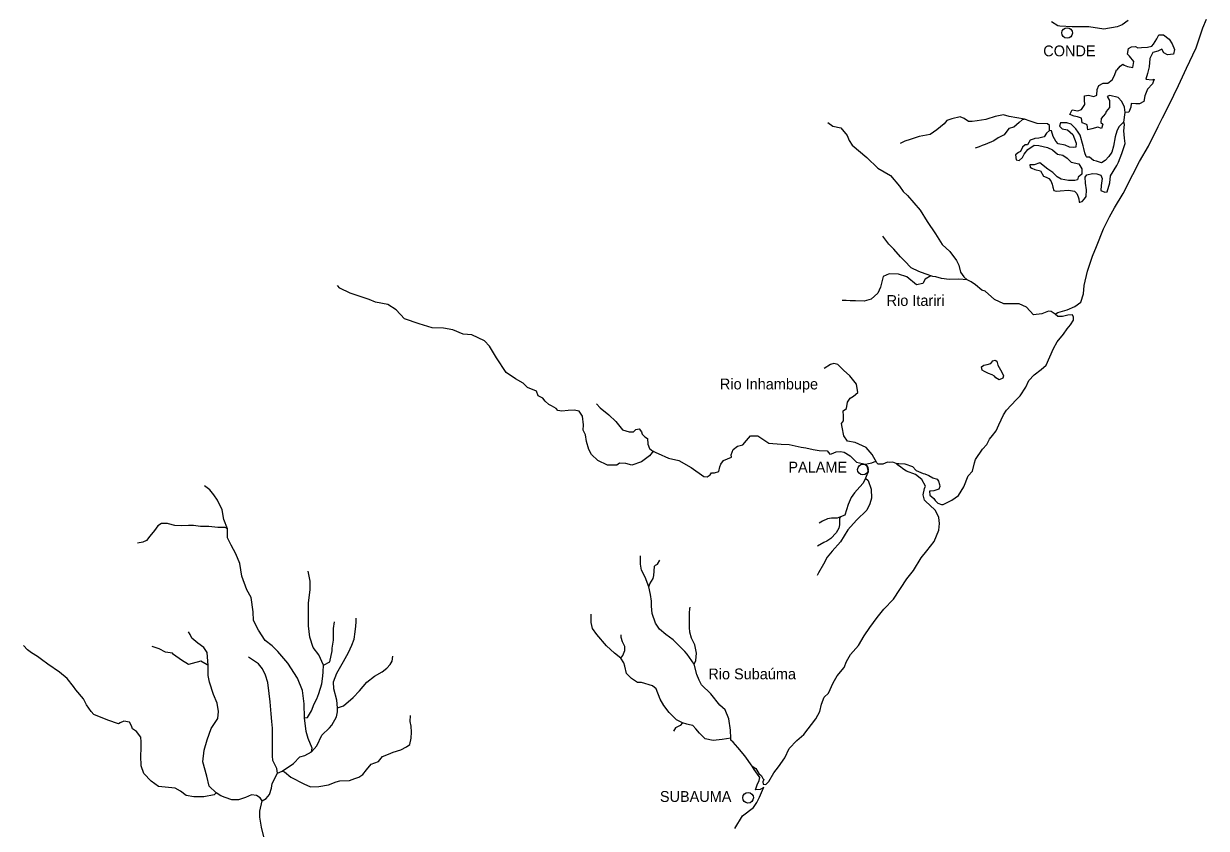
# Model space of a CAD drawing. Extents: x 662444 to 1640468, y 7452018 to 9606170.
# Drawn here: x 1241764 to 1315315, y 8633623 to 8683681 of the extents above; entities that cross this region are included whole.
import ezdxf

# ---------------------------------------------------------------- set-up
doc = ezdxf.new("R2010")
doc.units = 0
for name, color, linetype in [('Level 1', 7, 'Continuous'), ('Level 2', 7, 'Continuous'), ('Level 3', 7, 'Continuous')]:
    doc.layers.add(name, color=color, linetype=linetype)

msp = doc.modelspace()

# ---------------------------------------------------------------- linework, layer by layer
at = {"layer": 'Level 1'}
msp.add_line((1300438, 8667746), (1300438, 8667746), dxfattribs=at)
for points in [[(1310445, 8683882), (1310086, 8683602), (1309776, 8683487), (1308948, 8683342), (1308007, 8683490), (1307524, 8683492), (1306963, 8683473), (1306206, 8683515), (1306075, 8683552), (1305686, 8683797)], [(1311166, 8675098), (1311719, 8676053), (1312312, 8677286), (1312590, 8677825), (1312996, 8678628), (1313298, 8679222), (1313589, 8679839), (1314090, 8680919), (1314684, 8682174), (1315091, 8683412), (1315315, 8683964)], [(1310188, 8677544), (1310270, 8678155), (1310235, 8678490), (1310069, 8678840), (1309823, 8679081), (1309321, 8679217), (1309155, 8679155), (1309291, 8678906), (1309290, 8678460), (1309085, 8678209), (1309050, 8678098), (1308902, 8677924), (1308767, 8677782), (1308760, 8677537), (1308878, 8677423), (1308794, 8677157), (1308565, 8677241), (1308200, 8677129), (1307946, 8677080), (1307910, 8677393), (1307823, 8677429), (1307584, 8677502), (1307548, 8677804), (1307308, 8677888), (1307090, 8677916), (1306829, 8678024), (1306968, 8678310), (1307330, 8678267), (1307551, 8678350), (1307757, 8678657), (1307731, 8678914), (1307739, 8679193), (1307993, 8679242), (1308320, 8679144), (1308498, 8679239), (1308529, 8679584), (1308634, 8679827), (1308902, 8679976), (1309188, 8679979), (1309468, 8680184), (1309607, 8680448), (1309737, 8680801), (1309770, 8680811), (1309963, 8681029), (1310131, 8681170), (1310195, 8681090), (1310412, 8681006), (1310752, 8680963), (1310795, 8681330), (1310540, 8681649), (1310411, 8681787), (1310476, 8682142), (1310665, 8682237), (1310918, 8682264), (1311059, 8682182), (1311279, 8682187), (1311653, 8682211), (1311918, 8682270), (1312032, 8682401), (1312227, 8682731), (1312366, 8682983), (1312652, 8682987), (1313007, 8682710), (1313197, 8682415), (1313330, 8682065), (1313279, 8681788), (1312893, 8681731), (1312666, 8681871), (1312551, 8682086), (1312295, 8681970), (1311985, 8681878), (1311799, 8681504), (1311753, 8681004), (1311664, 8680582), (1311556, 8680228), (1311951, 8680195), (1312073, 8680237), (1311966, 8679927), (1311649, 8679601), (1311495, 8679181), (1311431, 8678838), (1311153, 8678700), (1310922, 8678684), (1310648, 8678713), (1310620, 8678480), (1310502, 8678182), (1310270, 8678155)], [(1305561, 8677032), (1305559, 8677355), (1305441, 8677447), (1304793, 8677476), (1304358, 8677610), (1303999, 8677742), (1303059, 8677912), (1302710, 8678011), (1302180, 8677902), (1301659, 8677737), (1301604, 8677717), (1301052, 8677631), (1300744, 8677594), (1300524, 8677589), (1300255, 8677786), (1300005, 8677882), (1299496, 8677761), (1299186, 8677647), (1299005, 8677440), (1298556, 8677084), (1298142, 8676794), (1297447, 8676656), (1296893, 8676470), (1296560, 8676367), (1296271, 8676230)], [(1303999, 8677742), (1303965, 8677721), (1303855, 8677701), (1303674, 8677528), (1303348, 8677235), (1303038, 8677154), (1302732, 8676772), (1302364, 8676581), (1302096, 8676388), (1301552, 8676168), (1301363, 8676106), (1301185, 8676022), (1300941, 8675928)], [(1306639, 8677505), (1306244, 8677504), (1306184, 8677305), (1306344, 8677145), (1306683, 8677080), (1307005, 8676792), (1307221, 8676251), (1307203, 8676007), (1307027, 8675967), (1306808, 8676006), (1306526, 8676125), (1306100, 8676214), (1305950, 8676363), (1305793, 8676669), (1305681, 8677006), (1305561, 8677032), (1305370, 8676869), (1305222, 8676650), (1304900, 8676547), (1304647, 8676532), (1304614, 8676510), (1304359, 8676439), (1304198, 8676142), (1304044, 8676147), (1303887, 8676006), (1303747, 8675731), (1303625, 8675667), (1303456, 8675515), (1303492, 8675202), (1303677, 8675164), (1303880, 8675359), (1303995, 8675557), (1304223, 8675852), (1304603, 8676121), (1304888, 8676102), (1305445, 8675975), (1305749, 8675822), (1306049, 8675558), (1306399, 8675504), (1306658, 8675319), (1306914, 8675055), (1307395, 8674953), (1307574, 8674659), (1307576, 8674324), (1307340, 8674130), (1307292, 8673975), (1307137, 8673923), (1306742, 8673934), (1306282, 8674013), (1306044, 8674142), (1305777, 8674417), (1305464, 8674626), (1304959, 8675029), (1304604, 8674894), (1304329, 8674901), (1304358, 8674756), (1304456, 8674697), (1304640, 8674603), (1305011, 8674515), (1305178, 8674187), (1305352, 8674138), (1305526, 8674055), (1305653, 8673896), (1305736, 8673704), (1305775, 8673502), (1305835, 8673300), (1305977, 8673252), (1306219, 8673279), (1306736, 8673332), (1307119, 8673255), (1307258, 8673106), (1307340, 8672914), (1307381, 8672779), (1307408, 8672578), (1307441, 8672577), (1307596, 8672617), (1307743, 8672781), (1307846, 8672934), (1307857, 8673335), (1307802, 8673749), (1307779, 8674129), (1307882, 8674282), (1308225, 8674362), (1308498, 8674333), (1308749, 8674259), (1308831, 8674045), (1308765, 8673623), (1308757, 8673311), (1308995, 8673204), (1309138, 8673212), (1309318, 8673775), (1309363, 8674220), (1309743, 8674857), (1309847, 8675066), (1310059, 8675596), (1310274, 8676226), (1310227, 8676550), (1310174, 8677009), (1310228, 8677398), (1310188, 8677544), (1310155, 8677545)], [(1310155, 8677545), (1309873, 8677262), (1309756, 8676987), (1309648, 8676644), (1309533, 8676056), (1309435, 8675679), (1309241, 8675417), (1309026, 8675166), (1308803, 8675027), (1308487, 8675125), (1308290, 8675175), (1308054, 8675371), (1307878, 8675375), (1307836, 8675421), (1307765, 8675646), (1307706, 8675915), (1307655, 8676073), (1307476, 8676746), (1307349, 8676939), (1307189, 8677133), (1307083, 8677259), (1306901, 8677431), (1306639, 8677505)], [(1291782, 8677529), (1292094, 8677298), (1292575, 8677208), (1292979, 8676718), (1293092, 8676403), (1293293, 8676130), (1294206, 8675348), (1294891, 8674694), (1295670, 8674239), (1296234, 8673566), (1296456, 8673237), (1296735, 8672984), (1297512, 8672083), (1297955, 8671380), (1298472, 8670597), (1298883, 8669939), (1299365, 8669503), (1299779, 8668957), (1299914, 8668652), (1300023, 8668214), (1300224, 8667930), (1300438, 8667746)], [(1307719, 8667395), (1307930, 8668293), (1308229, 8669210), (1308487, 8669828), (1308912, 8670909), (1309283, 8671658), (1309606, 8672218), (1310146, 8673118), (1310738, 8674295), (1311166, 8675098)], [(1305904, 8665615), (1305655, 8665767), (1305502, 8665804), (1305092, 8665637), (1304574, 8665573), (1304126, 8666042), (1303670, 8666244), (1302715, 8666258), (1302140, 8666519), (1301550, 8667036), (1301343, 8667098), (1300968, 8667431), (1300699, 8667628), (1300438, 8667746), (1299912, 8667783), (1299330, 8667765), (1298838, 8667822), (1298489, 8667921), (1298314, 8667948), (1297825, 8668128), (1297433, 8668272), (1296967, 8668485), (1296551, 8668931), (1296294, 8669183), (1295878, 8669662), (1295568, 8669972), (1295197, 8670461)], [(1298185, 8667995), (1297827, 8667793), (1297688, 8667518), (1297290, 8667429), (1296678, 8667924), (1296166, 8668094), (1295585, 8668121), (1295207, 8667952), (1295047, 8667287), (1294884, 8666924), (1294478, 8666533), (1294025, 8666423), (1293488, 8666437), (1293170, 8666445), (1292917, 8666452), (1292665, 8666459)], [(1280885, 8657082), (1280930, 8657115), (1280680, 8656798), (1280177, 8656421), (1279590, 8656214), (1279220, 8656324), (1278825, 8656334), (1278647, 8656216), (1278065, 8656209), (1277470, 8656514), (1277084, 8656870), (1276917, 8657186), (1276777, 8657691), (1276700, 8658106), (1276553, 8658388), (1276573, 8658722), (1276521, 8659258), (1276310, 8659576), (1276005, 8659639), (1275631, 8659616), (1275235, 8659570), (1274984, 8659621), (1274877, 8659736), (1274596, 8659899), (1274423, 8659993), (1274187, 8660188), (1274060, 8660381), (1273768, 8660522), (1273655, 8660815), (1273101, 8661041), (1272834, 8661315), (1272359, 8661595), (1271776, 8661978), (1271163, 8662885), (1270732, 8663609), (1270423, 8663952), (1269631, 8664317), (1269106, 8664364), (1268455, 8664637), (1267865, 8664730), (1267164, 8664760), (1266358, 8665014), (1265456, 8665327), (1264921, 8665875), (1264414, 8666211), (1263639, 8666354), (1263249, 8666531), (1262574, 8666749), (1262074, 8666906), (1261423, 8667223), (1261274, 8667383)], [(1300778, 8655851), (1300891, 8656361), (1300962, 8656560), (1301386, 8657218), (1301668, 8657511), (1301830, 8657830), (1302012, 8658059), (1302239, 8658354), (1302403, 8658718), (1302694, 8659346), (1302889, 8659641), (1303487, 8660272), (1303736, 8660533), (1304079, 8661059), (1304266, 8661478), (1304616, 8661836), (1305042, 8662159), (1305357, 8662441), (1305813, 8663477), (1306033, 8663883), (1306441, 8664374), (1306658, 8664692), (1306863, 8664954), (1307046, 8665228), (1307062, 8665417), (1306989, 8665564), (1306692, 8665538), (1306371, 8665458), (1306251, 8665461), (1306086, 8665465), (1305904, 8665615), (1306071, 8665711), (1306668, 8665885), (1307135, 8666095), (1307505, 8666364), (1307672, 8666883), (1307719, 8667395)], [(1296028, 8656313), (1295811, 8656408), (1295624, 8656391), (1295492, 8656395), (1295193, 8656280), (1294908, 8656276), (1294822, 8656368), (1294529, 8656889), (1294168, 8657322), (1293473, 8657630), (1292992, 8657699), (1292771, 8658039), (1292676, 8658588), (1292616, 8658801), (1292752, 8658976), (1292759, 8659255), (1292735, 8659590), (1292926, 8659741), (1293002, 8660140), (1293163, 8660381), (1293363, 8660498), (1293644, 8660736), (1293548, 8661263), (1293144, 8661764), (1292759, 8662120), (1292395, 8662486), (1292145, 8662548), (1291934, 8662476), (1291554, 8662230)], [(1302004, 8661840), (1301765, 8661924), (1301515, 8662042), (1301375, 8662135), (1301326, 8662337), (1301482, 8662444), (1301681, 8662484), (1301913, 8662544), (1302027, 8662709), (1302182, 8662749), (1302279, 8662691), (1302338, 8662433), (1302590, 8661991), (1302693, 8661765), (1302657, 8661621), (1302423, 8661516), (1302229, 8661655), (1302144, 8661758), (1302004, 8661840)], [(1277397, 8660038), (1277610, 8659787), (1278158, 8659338), (1278597, 8658925), (1279000, 8658413), (1279414, 8658291), (1279699, 8658284), (1279845, 8658425), (1280033, 8658476), (1280182, 8658282), (1280233, 8658136), (1280404, 8657975), (1280555, 8657871), (1280579, 8657514), (1280681, 8657244), (1280885, 8657082), (1281233, 8656951), (1281872, 8656655), (1282516, 8656505), (1283272, 8656061), (1284058, 8655517), (1284266, 8655489), (1284467, 8655617), (1284547, 8655738), (1284722, 8655733), (1284988, 8655826), (1285062, 8656114), (1285121, 8656280), (1285291, 8656509), (1285791, 8656719), (1285773, 8656865), (1285891, 8657185), (1286148, 8657390), (1286480, 8657481), (1286707, 8657754), (1286956, 8658037), (1287417, 8658047), (1288107, 8657594), (1288873, 8657518), (1289377, 8657494), (1290119, 8657329), (1290414, 8657288), (1290853, 8657184), (1291244, 8657128)], [(1291244, 8657128), (1291737, 8657108), (1291896, 8656892), (1292006, 8656911), (1292284, 8657049), (1292559, 8657075), (1292788, 8657024), (1293166, 8656802), (1293561, 8656402), (1294118, 8656275), (1294295, 8656326), (1294515, 8656365), (1294765, 8656469)], [(1285998, 8633607), (1286469, 8634408), (1287151, 8634924), (1287368, 8635231), (1287530, 8635572), (1287717, 8635990), (1287787, 8636156), (1287565, 8636050), (1287279, 8636013), (1287375, 8636323), (1287514, 8636609), (1287541, 8636787), (1287393, 8636991), (1287203, 8637275), (1287067, 8637491), (1287293, 8637340), (1287482, 8637045), (1287643, 8636895), (1287737, 8636726), (1287801, 8636657), (1287742, 8636514), (1287749, 8636369), (1287913, 8636353), (1288116, 8636537), (1288426, 8637086), (1288699, 8637458), (1289098, 8638004), (1289366, 8638588), (1289840, 8639088), (1290278, 8639466), (1291038, 8640427), (1291270, 8640889), (1291381, 8641354), (1291546, 8641785), (1291816, 8642023), (1292108, 8642672), (1292350, 8643101), (1292781, 8643635), (1292933, 8643999), (1293095, 8644296), (1293181, 8644438), (1293684, 8644994), (1294029, 8645597), (1294394, 8646123), (1294849, 8646735), (1295258, 8647259), (1295857, 8647889), (1296691, 8649138), (1297111, 8649662), (1297571, 8650441), (1297934, 8650877), (1298389, 8651467), (1298671, 8652173), (1298726, 8652595), (1298670, 8652965), (1298474, 8653394), (1298099, 8653738), (1297895, 8653933), (1297789, 8654048), (1297699, 8654373), (1297797, 8654761), (1297856, 8654904), (1297615, 8655334), (1297228, 8655635), (1296674, 8655839), (1296436, 8655979), (1296286, 8656106), (1296124, 8656210), (1296028, 8656313), (1296182, 8656320), (1296565, 8656299), (1297044, 8656130), (1297268, 8655890), (1297712, 8655700), (1297800, 8655686), (1298049, 8655568), (1298309, 8655427), (1298570, 8655353), (1298665, 8655217), (1298714, 8655004), (1298733, 8654881), (1298685, 8654715), (1298364, 8654612), (1298166, 8654606), (1298100, 8654608), (1298126, 8654351), (1298373, 8654143), (1298446, 8654019), (1298607, 8653858), (1298835, 8653774), (1298945, 8653771), (1299479, 8654047), (1299892, 8654325), (1300225, 8654874), (1300496, 8655558), (1300778, 8655851)], [(1294118, 8656275), (1294202, 8656161), (1294262, 8655926), (1294280, 8655780), (1294199, 8655615), (1294128, 8655417), (1293965, 8655098), (1293773, 8654869), (1293434, 8654487), (1293228, 8654203), (1293041, 8653762), (1292837, 8653110), (1292560, 8653006), (1292360, 8652911), (1292009, 8652909), (1291745, 8652883), (1291444, 8652723), (1291233, 8652618)], [(1259675, 8638380), (1259714, 8638613), (1259456, 8639221), (1259325, 8639648), (1259237, 8640508), (1259205, 8641378), (1259106, 8642205), (1258785, 8642959), (1258185, 8643899), (1257568, 8644617), (1257215, 8644983), (1256785, 8645317), (1256363, 8645952), (1256061, 8646561), (1256031, 8647096), (1255911, 8647979), (1255649, 8648454), (1255331, 8649309), (1255198, 8650092), (1254961, 8650700), (1254679, 8651230), (1254449, 8651693), (1254442, 8652261), (1254215, 8652835), (1254099, 8653440), (1253829, 8654048), (1253585, 8654366), (1253341, 8654684), (1253008, 8654938)], [(1294128, 8655417), (1294277, 8655256), (1294460, 8654728), (1294489, 8654169), (1294392, 8653804), (1294195, 8653419), (1293553, 8652790), (1293010, 8652191), (1292562, 8651445), (1292053, 8650868), (1291736, 8650497), (1291516, 8650057), (1291194, 8649520), (1291102, 8649344)], [(1254442, 8652261), (1254301, 8652332), (1253841, 8652343), (1253272, 8652391), (1252757, 8652393), (1252331, 8652460), (1252024, 8652467), (1251596, 8652434), (1251158, 8652456), (1250777, 8652566), (1250701, 8652590), (1250328, 8652577), (1250105, 8652438), (1249900, 8652143), (1249607, 8651794), (1249413, 8651520), (1249170, 8651426), (1248850, 8651356)], [(1292560, 8653006), (1292492, 8652918), (1292503, 8652506), (1292464, 8652295), (1292292, 8651998), (1291954, 8651662), (1291718, 8651479), (1291519, 8651395), (1291140, 8651182)], [(1287067, 8637491), (1286612, 8638127), (1286177, 8638662), (1285890, 8638993), (1285739, 8639109), (1285743, 8639231), (1285712, 8639734), (1285610, 8640439), (1285384, 8640991), (1285052, 8641290), (1284501, 8641996), (1283923, 8642546), (1283777, 8642840), (1283634, 8643200), (1283464, 8643829), (1283031, 8644465), (1282882, 8644625), (1282155, 8645346), (1281693, 8645681), (1281306, 8646004), (1281053, 8646389), (1280861, 8646985), (1280818, 8647454), (1280804, 8647756), (1280750, 8648170), (1280641, 8648641), (1280405, 8649249), (1280197, 8649678), (1280119, 8650047), (1280122, 8650571)], [(1259237, 8640508), (1259413, 8640514), (1259665, 8640931), (1259829, 8641373), (1260002, 8641680), (1260120, 8642011), (1260300, 8642608), (1260367, 8643097), (1260396, 8643352), (1260406, 8643764), (1260127, 8644418), (1259766, 8644873), (1259564, 8645513), (1259483, 8646217), (1259469, 8646964), (1259475, 8647621), (1259574, 8648476), (1259587, 8648999), (1259461, 8649615)], [(1280641, 8648641), (1280701, 8648828), (1280907, 8649157), (1280945, 8649346), (1280974, 8649624), (1280993, 8649924), (1281050, 8650001), (1281172, 8650053), (1281321, 8650306)], [(1256701, 8633098), (1256552, 8633692), (1256447, 8634319), (1256446, 8634687), (1256605, 8635340), (1256839, 8635490), (1257043, 8635730), (1257173, 8636116), (1257214, 8636416), (1257559, 8637053), (1257847, 8637179), (1258539, 8637652), (1258933, 8638076), (1259253, 8638157), (1259675, 8638380), (1260003, 8638750), (1260316, 8639422), (1260777, 8639878), (1260935, 8640052), (1261211, 8640557), (1261274, 8640867), (1261292, 8641123), (1261238, 8641604), (1261059, 8642310), (1261027, 8642746), (1261249, 8643275), (1261662, 8643999), (1261962, 8644571), (1262182, 8645022), (1262312, 8645397), (1262378, 8645852), (1262420, 8646197), (1262438, 8646464), (1262444, 8646697)], [(1285743, 8639231), (1285214, 8639156), (1284642, 8639083), (1284152, 8639196), (1283788, 8639540), (1283565, 8639813), (1283373, 8640019), (1283177, 8640069), (1283003, 8640096), (1282742, 8640181), (1282363, 8640381), (1281915, 8640827), (1281586, 8641259), (1281345, 8641656), (1281099, 8642309), (1280873, 8642493), (1280177, 8642690), (1279936, 8642696), (1279559, 8642952), (1279260, 8643260), (1279152, 8643720), (1279080, 8643923), (1278901, 8644206), (1278515, 8644528), (1278012, 8644987), (1277405, 8645672), (1277130, 8646058), (1277052, 8646428), (1277065, 8646940)], [(1283464, 8643829), (1283558, 8644060), (1283614, 8644516), (1283507, 8645043), (1283299, 8645449), (1283188, 8645820), (1283163, 8646111), (1283166, 8646668), (1283176, 8647035), (1283193, 8647269), (1283218, 8647380)], [(1260406, 8643764), (1260796, 8643988), (1260956, 8644675), (1260960, 8644831), (1261028, 8645330), (1261035, 8646054), (1261101, 8646465)], [(1256605, 8635340), (1256467, 8635522), (1256241, 8635661), (1255924, 8635703), (1255570, 8635545), (1255127, 8635389), (1254711, 8635389), (1254299, 8635544), (1254027, 8635651), (1253736, 8635826), (1253309, 8636238), (1253150, 8636877), (1252909, 8637763), (1252994, 8638485), (1253175, 8639127), (1253423, 8639833), (1253833, 8640458), (1253888, 8640902), (1253803, 8641416), (1253576, 8641957), (1253321, 8642710), (1253233, 8643135), (1253238, 8643748), (1253171, 8644552), (1252971, 8644880), (1252594, 8645146), (1252230, 8645456), (1252126, 8645681), (1252009, 8645840)], [(1278901, 8644206), (1279026, 8644370), (1279144, 8644690), (1279151, 8644935), (1279005, 8645218), (1278924, 8645487), (1278929, 8645654)], [(1253736, 8635826), (1253613, 8635707), (1252974, 8635578), (1252350, 8635594), (1251870, 8635673), (1251515, 8635928), (1251180, 8636114), (1250765, 8636159), (1250153, 8636230), (1249690, 8636554), (1249232, 8637044), (1249068, 8637516), (1249051, 8638141), (1249063, 8638597), (1249063, 8639009), (1249048, 8639299), (1248772, 8639640), (1248524, 8639814), (1248474, 8639993), (1248338, 8640219), (1248000, 8640284), (1247767, 8640189), (1247656, 8640125), (1246993, 8640343), (1246126, 8640710), (1245955, 8640893), (1245681, 8641312), (1245493, 8641673), (1245014, 8642242), (1244855, 8642446), (1244462, 8642935), (1243990, 8643337), (1243269, 8643834), (1242881, 8644122), (1242623, 8644307), (1242256, 8644539), (1242009, 8644723), (1241764, 8644997)], [(1253238, 8643748), (1253184, 8643794), (1252774, 8644027), (1252244, 8643885), (1252012, 8643813), (1251570, 8644091), (1251075, 8644438), (1251022, 8644517), (1250575, 8644584), (1250185, 8644795), (1249761, 8644928)], [(1257559, 8637053), (1257512, 8637344), (1257251, 8637852), (1257236, 8638142), (1257241, 8638732), (1257230, 8639156), (1257237, 8639846), (1257192, 8640260), (1257161, 8640740), (1257093, 8641499), (1257029, 8642013), (1256959, 8642706), (1256806, 8643144), (1256619, 8643539), (1256364, 8643857), (1256235, 8643950), (1255750, 8644263)], [(1261292, 8641123), (1261656, 8641236), (1262261, 8641755), (1262656, 8642180), (1263098, 8642725), (1263578, 8643081), (1264068, 8643369), (1264359, 8643595), (1264562, 8643813), (1264677, 8644033), (1264729, 8644343)], [(1257847, 8637179), (1257989, 8637142), (1258374, 8636798), (1259186, 8636398), (1259608, 8636198), (1260112, 8636218), (1260729, 8636336), (1261194, 8636524), (1261437, 8636574), (1262029, 8636592), (1262350, 8636717), (1262604, 8636800), (1262861, 8636982), (1263087, 8637266), (1263381, 8637615), (1263824, 8637782), (1264084, 8638087), (1264450, 8638233), (1264749, 8638371), (1265224, 8638503), (1265580, 8638694), (1265770, 8638845), (1265868, 8639233), (1265888, 8639611), (1265865, 8639979), (1265807, 8640271), (1265817, 8640638)], [(1282742, 8640181), (1282584, 8640029), (1282306, 8639869), (1282180, 8639672)]]:
    msp.add_lwpolyline(points, dxfattribs=at)
at = {"layer": 'Level 2'}
for centre, major_axis in [((1306656, 8683102), (329, -7)), ((1293955, 8655945), (331, -7)), ((1286816, 8635524), (329, -7))]:
    msp.add_ellipse(centre, major_axis=major_axis, ratio=0.999997, dxfattribs=at)

# ---------------------------------------------------------------- texts
at = {"layer": 'Level 3'}
for s, height, p in [('CONDE', 674, (1305172, 8681649)), ('Rio Itariri', 673.54, (1295429, 8666123)), ('Rio Inhambupe', 673.3, (1285062, 8660927)), ('PALAME', 673.2, (1289321, 8655758)), ('Rio Subaúma', 672.88, (1284343, 8642894)), ('SUBAUMA', 672.7, (1281331, 8635268))]:
    msp.add_text(s, height=height, dxfattribs=at).set_placement(p)

doc.saveas('drawing.dxf')
